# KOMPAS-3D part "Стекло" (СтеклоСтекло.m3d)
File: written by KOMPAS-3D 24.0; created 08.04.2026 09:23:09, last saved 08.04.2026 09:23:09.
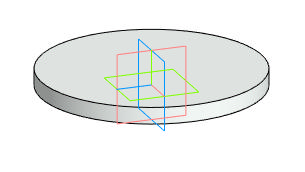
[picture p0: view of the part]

Document properties: Автор: Main; Полное имя файла: D:\DN.ru Аутсерс\Стекло смотровое DN.ru\Исходники\Стекло смотровое DN.ru SG2-34G-F тип В ГОСТ 21836-2021 Ду200 Ру16, углеродистая сталь, фланцевое\СтеклоСтекло.m3d

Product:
- Body: Твердое тело1  | qty 1
- Part/product: Стекло

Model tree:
1. Твердое тело1  (labels: Твердое тело1)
